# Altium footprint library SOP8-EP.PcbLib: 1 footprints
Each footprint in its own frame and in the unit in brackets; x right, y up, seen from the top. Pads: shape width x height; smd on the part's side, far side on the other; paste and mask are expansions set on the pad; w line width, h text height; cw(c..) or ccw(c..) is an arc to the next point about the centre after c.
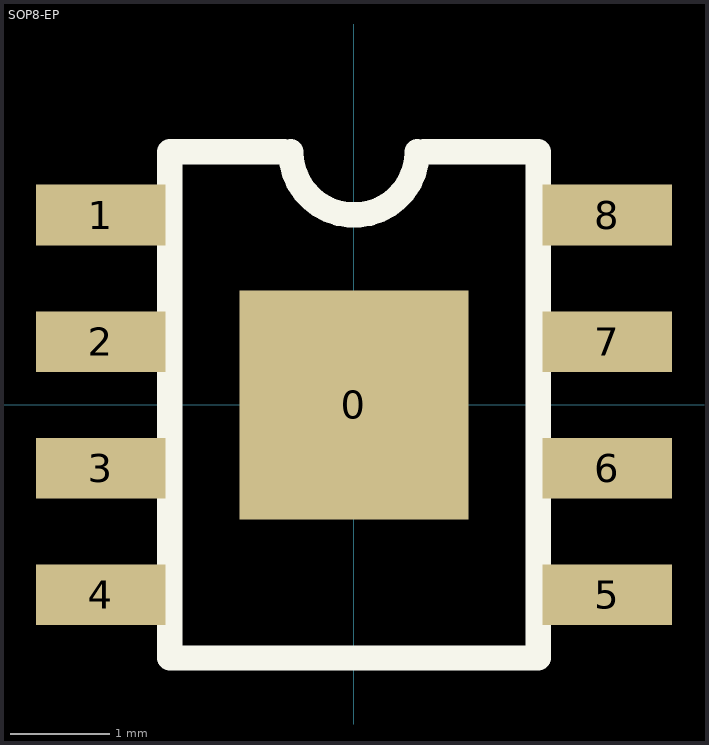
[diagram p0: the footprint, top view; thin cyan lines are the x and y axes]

## SOP8-EP [mm]
pads (9):
  rect 2.3x2.3 smd: 0(0,0)
  rect 1.3x0.61 smd: 1(-2.544,1.905) 2(-2.544,0.635) 3(-2.544,-0.635) 4(-2.544,-1.905) 5(2.544,-1.905) 6(2.544,-0.635) 7(2.544,0.635) 8(2.544,1.905)
Top Overlay:
  lines w0.254: -0.7,2.54 -1.85,2.54 -1.85,-2.54 1.85,-2.54 1.85,2.54 0.7,2.54 ; -0.635,2.54 ccw(c0,2.54) 0.635,2.54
